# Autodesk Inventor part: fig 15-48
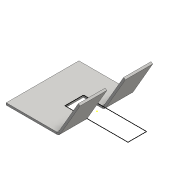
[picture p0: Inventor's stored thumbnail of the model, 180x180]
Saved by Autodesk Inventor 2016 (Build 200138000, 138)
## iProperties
Created: 2015-07
Part Number: fig 15-48
Material: Generic
Document SubType Name: Sheet Metal
Designer: Sandeep
Density: 1 g/cm^3
Sheet Metal Rule: Default_mm
Appearance: Default
Author: Sandeep
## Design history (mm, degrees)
node "Face1"
  sketch "Sketch1"
    geometry: L1 (-12.609, 8.313)-(0, 8.313); L2 (0, 8.313)-(0, -9.006); L3 (0, -9.006)-(-12.609, -9.006); L4 (-12.609, -9.006)-(-12.609, 8.313); 1 further point
    constraints: 8 end point, 2 parallel, 1 horizontal, 1 perpendicular
node "Flange1"
sketch "Sketch3"
  geometry: L1 (9.998, 1.795)-(-5.034, 1.795); L2 (-5.034, 1.795)-(-5.034, -2.633); L3 (-5.034, -2.633)-(9.998, -2.633); L4 (9.998, -2.633)-(9.998, 1.795); 1 further point
  constraints: 8 end point, 2 parallel, 1 horizontal, 1 perpendicular
cut "Cut1" sketch "Sketch3" dims "d11" = 0.5 (= Thickness), "d12" = 0
body "Solid1"
face "Plate1" dims "Thickness" = 0.5
sketch "Sketch2"
  geometry: L1 through (-8.66, 0) direction (1, 0); L2 through (0, 5) direction (0, 1); L3 (0, 10)-(-17.319, 10); L4 (-17.319, 10)-(-17.319, 0)
  constraints: 6 end point, 1 horizontal, 1 perpendicular, 1 vertical
face "Plate2" dims "d1" = 0.5 (= BendReliefWidth), "d2" = 0.25 (= BendReliefDepth), "d3" = 1 (= MinimumRemnant), "d4" = 0.5 (= BendRadius), "d5" = 10, "d6" = 60 deg, "d7" = 0.5 (= BendRadius), "d8" = 2 (= CornerReliefSize), "d9" = 0.5 (= GapSize), "d10" = 0.5 (= JacobiRadiusSize), "SeamGap" = 0.01, "Thickness" = 0.5
bend "Bend1" dims "d1" = 0.5 (= BendReliefWidth), "d2" = 0.25 (= BendReliefDepth), "d3" = 1 (= MinimumRemnant), "d4" = 0.5 (= BendRadius), "d5" = 10, "d6" = 60 deg, "d7" = 0.5 (= BendRadius), "SeamGap" = 0.01, "Thickness" = 0.5
feature "Corner1" dims "d5" = 10, "d6" = 60 deg, "d8" = 2 (= CornerReliefSize), "d9" = 0.5 (= GapSize), "d10" = 0.5 (= JacobiRadiusSize)
other parameters: "BendRadius" = 0.5 (= Thickness), "BendReliefWidth" = 0.5 (= Thickness), "BendReliefDepth" = 0.25 (= 0.5 x Thickness), "CornerReliefSize" = 2 (= 4 x Thickness), "MinimumRemnant" = 1 (= 2 x Thickness), "TransitionRadius" = 0.5 (= BendRadius), "JacobiRadiusSize" = 0.5 (= BendRadius), "GapSize" = 0.5 (= Thickness), "d0" = 0.5 (= BendRadius)
